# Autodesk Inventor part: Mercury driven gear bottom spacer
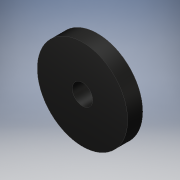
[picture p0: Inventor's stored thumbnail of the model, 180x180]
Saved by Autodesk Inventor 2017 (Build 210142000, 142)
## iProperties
Created: 2016-07
Part Number: Mercury driven gear bottom spacer
Material: Generic
Document SubType Name: Modeling
Designer: Stan
Density: 1 g/cm^3
Appearance: Glossy - Black
Author: Stan
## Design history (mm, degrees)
sketch "Sketch1"
  geometry: C1 r 2.159 at (0, 0); C2 r 9.525 at (0, 0); 1 further point
  constraints: 2 centre point, 2 coincident
  dimensions: "d0" = 4.318 diameter of C1; "d1" = 19.05 diameter of C2
extrude "Extrusion1" new body sketch "Sketch1" distance "d2" = 3.175; taper "d3" = 0 deg
body "Solid1"
